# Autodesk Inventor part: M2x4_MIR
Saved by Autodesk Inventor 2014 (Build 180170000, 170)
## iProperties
Created: 2015-05
Part Number: M2x4_MIR
Material: 일반
Vendor: CBT Solutions
Document SubType Name: 모델링
Designer: Administrator
Appearance: 기본값
Company: 한국ATC센터
Author: KYOUNG IL JANG
Comments: 파생
d0: 1.000 ul
d0_1: 1.000 ul
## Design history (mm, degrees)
derived "M2x4.ipt" dims count "d0" = 1
feature "솔리드1::M2x4.ipt" dims count "d0" = 1
tag "피쳐 태그1"
node "솔리드1"
other parameters: "d0_1" = 1
